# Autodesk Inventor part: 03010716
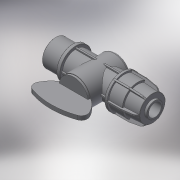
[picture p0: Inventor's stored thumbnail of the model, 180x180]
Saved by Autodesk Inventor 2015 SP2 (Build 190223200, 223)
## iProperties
Created: 2017-05
Part Number: 03010716
Material: Generic
Description: PLASSON 1/4 TURN VALVE MALE THREADED X COMPRESSION 16X3/4"
Document SubType Name: Modeling
Designer: KIM
Density: 1 g/cm^3
Appearance: Default
Author: KIM
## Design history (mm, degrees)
derived "03010.ipt"
feature "Solid1::03010.ipt"
tag "TaggingFeature1"
body "Solid1"
other parameters: "d0" = 99, "d1" = 17, "d3" = 26.441, "d4" = 12.59228, "d5" = 16, "d6" = 34, "d8" = 17, "d9" = 33, "d10" = 2.475, "d11" = 30.6, "d12" = 27.2, "d13" = 25.5, "d14" = 2.475, "d15" = 26.441, "d16" = 31.7292, "d17" = 20.4, "d19" = 0.245, "d25" = 1.47, "d26" = 0, "d27" = 4.9, "d29" = 360 deg, "d31" = 49, "d32" = 4.95, "d33" = 18.7, "d34" = 24.5, "d36" = 14.96, "d38" = 2.45, "d39" = 29.0851, "d40" = 1.47, "d41" = 0, "d43" = 360 deg, "d45" = 49, "d46" = 52, "d47" = 45, "d48" = 4, "d49" = 0, "d50" = 29, "d51" = 2, "d52" = 0, "d53" = 8, "d59" = 40 deg, "d60" = 25.5, "d62" = 3.0525, "L_" = 99, "A_" = 49, "E_" = 34, "l_" = 17, "l_1" = 15, "l_2" = 17, "R_" = 26.441, "d_" = 16, "d61" = 30.525
